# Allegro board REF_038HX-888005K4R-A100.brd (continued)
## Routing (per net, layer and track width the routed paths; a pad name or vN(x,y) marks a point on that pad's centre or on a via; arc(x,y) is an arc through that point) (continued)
D12301: length 268.6
  TOP w0.231: v1(203.52,224.03) 203.32,224.23 SITE2.118
  L03_SIGNAL w0.145: v1(203.52,224.03) 203.52,219.99 202.45,218.92 202.45,210.06 205.53,206.99 205.53,206.13 205.78,205.88 205.78,204.47 206,204.25 206,200.67 205.7,200.36 204.68,200.36 202.45,198.13 202.45,183.27 198,178.81 198,167.65 195.38,165.03 195.38,160.45 188.92,153.99 188.92,141.88 182.51,135.47 182.51,133.73 181.29,132.52 181.29,114.03 179.54,112.28 163.03,112.28 144.41,93.67 144.41,58.48 133.56,47.62 97.42,47.62 D123.01
D12302: length 218.4
  TOP w0.231: SITE2.161 190.93,212.03 v1(189.92,213.03)
  L03_SIGNAL w0.145: D123.02 103.77,70.48 131.14,70.48 134.89,74.23 134.89,119.16 147.59,131.86 147.59,148.59 153.94,154.94 153.94,157.48 156.48,160.02 156.48,161.11 171.08,175.72 171.08,179.07 178.06,186.04 178.06,197.59 183.23,202.76 186.32,202.76 187.02,203.46 187.02,207.77 187.66,208.42 187.66,210.77 v1(189.92,213.03)
D12303: length 258.3
  L03_SIGNAL w0.145: D123.03 101.81,48.32 133.27,48.32 143.72,58.77 143.72,94.15 162.56,112.99 179.27,112.99 180.5,114.22 180.5,132.65 181.81,133.97 181.81,135.95 187.96,142.1 187.96,154.37 193.35,159.75 193.35,168.95 195.11,170.71 195.11,178.93 201.81,185.63 201.81,189.8 200.94,190.66 200.94,197.65 205.16,201.87 205.16,205.6 201.71,209.06 201.71,222.14 v1(202.16,222.59)
D12304: length 212.7
  TOP w0.231: SITE2.160 191.92,212.43 v1(191.32,213.03)
  L03_SIGNAL w0.145: D123.04 108.22,69.85 131.41,69.85 135.52,73.97 135.52,118.9 148.22,131.6 148.22,148.41 155.21,155.39 155.21,157.48 157.75,160.02 157.75,161.19 172.35,175.8 172.35,179.07 179.6,186.31 179.6,197.3 183.79,201.49 186.5,201.49 187.97,202.96 187.97,207.66 188.5,208.2 188.5,210.21 v1(191.32,213.03)
D12305: length 282.8
  TOP w0.231: SITE2.150 198.71,216.43 v1(199.71,217.43)
  L03_SIGNAL w0.145: v1(199.71,217.43) 201.07,216.07 201.07,207.79 204.15,204.71 204.15,201.65 200.31,197.81 200.31,190.4 201.17,189.53 201.17,185.89 194.47,179.2 194.47,171.45 185.83,162.81 185.83,143.21 178.45,135.82 178.45,115.44 177.89,114.88 176.34,114.88 175.66,115.56 175.66,130.86 175.29,131.23 174.14,131.23 173.66,130.75 173.66,116.07 172.71,115.11 162.37,115.11 143.14,95.89 143.14,59.01 133.03,48.89 106.31,48.89 D123.05
D12306: length 215.8
  TOP w0.231: SITE2.159 192.92,212.83 v1(192.72,213.03)
  L03_SIGNAL w0.145: D123.06 102.89,59.44 108.06,59.44 108.3,59.21 108.3,58.16 109.02,57.43 113.18,57.43 113.4,57.65 113.4,65.55 116.43,68.58 131.93,68.58 136.79,73.44 136.79,118.37 149.49,131.07 149.49,144.14 157.11,151.76 157.11,154.31 160.23,157.42 160.23,158.55 173.91,172.23 173.91,176.18 180.87,183.14 180.87,196.77 184.4,200.3 189.17,200.3 190.23,201.36 190.23,210.27 192.55,212.59 192.55,212.86 v1(192.72,213.03)
D12307: length 225.4
  TOP w0.231: SITE2.164 198.71,210.83 199.71,209.83 v1(199.84,209.83)
  L03_SIGNAL w0.145: v1(199.84,209.83) 199.84,209.7 200.23,209.32 200.23,206.84 199.36,205.98 198.89,205.98 198.55,205.64 198.55,205.11 198.91,204.75 198.91,185.9 192.59,179.59 192.59,170.73 185.05,163.19 185.05,160.66 173.62,149.22 173.62,147.95 169.81,144.14 169.81,140.33 162.83,133.35 162.83,132.98 142.51,112.66 142.51,59.27 132.77,49.53 110.76,49.53 D123.07
D12308: length 210.6
  TOP w0.231: SITE2.163 192.92,211.23 v1(192.72,211.03)
  L03_SIGNAL w0.145: v1(192.72,211.03) 191.38,209.7 191.38,199.47 191.7,199.15 191.7,193.96 191.04,193.3 191.04,186.23 185.21,180.39 185.21,177.76 176.77,169.32 174.67,169.32 162.19,156.84 162.19,154.31 159.02,151.13 159.02,148.59 152.03,141.6 152.03,131.23 138.06,117.26 138.06,63.76 137.32,63.02 122.11,63.02 121.01,61.91 121.01,57.85 120.01,56.85 108.52,56.85 D123.08
D12309: length 210.7
  L03_SIGNAL w0.145: v1(198.77,207.69) 198.03,206.94 198.03,205.86 198.02,205.85 198.02,204.89 198.38,204.54 198.38,189.79 198.33,189.74 198.33,186.23 191.95,179.85 191.95,173.27 190.71,172.03 190.71,170.76 179.97,160.02 179.97,159.38 169.81,149.22 169.81,146.69 167.27,144.14 167.27,141.6 158.38,132.71 158.38,130.81 141.87,114.3 141.87,59.54 132.5,50.16 115.2,50.16 D123.09
D12310: length 205.8
  TOP w0.231: SITE2.155 192.92,214.43 v1(192.72,214.63)
  L03_SIGNAL w0.145: v1(192.72,214.63) 191.98,213.89 191.98,212.81 189.6,210.43 189.6,201.63 188.93,200.96 184.15,200.96 180.23,197.03 180.23,185.68 172.99,178.44 172.99,172.3 159.65,158.97 159.65,158.12 156.48,154.94 156.48,152.4 148.86,144.78 148.86,131.34 136.16,118.64 136.16,73.71 131.67,69.22 114.49,69.22 110.7,65.42 110.7,59.75 D123.10
D12311: length 210.4
  TOP w0.231: v1(198.44,209.83) 198.32,209.83 197.72,210.43 SITE2.165
  L03_SIGNAL w0.145: D123.11 119.65,50.8 132.24,50.8 141.24,59.8 141.24,114.56 157.75,131.07 157.75,133.35 166.64,142.24 166.64,144.78 169.18,147.32 169.18,149.86 178.7,159.38 178.7,161.29 191.26,173.84 191.26,180.14 197.58,186.46 197.58,200.99 197.29,201.28 197.29,204.93 197.47,205.12 197.47,208.99 198.32,209.83 v1(198.44,209.83)
D12312: length 282.8
  TOP w0.231: SITE2.151 192.92,216.03 v1(192.72,216.23)
  L03_SIGNAL w0.145: v1(192.72,216.23) 193.45,215.5 193.45,212.62 190.81,209.98 190.81,201.08 189.41,199.68 184.79,199.68 181.57,196.45 181.57,190.33 182.08,189.81 189.74,189.81 190.22,189.33 190.22,187.93 190.01,187.72 184.38,187.72 183.84,187.19 183.84,185.01 184.21,184.64 184.21,178.96 179.41,174.16 178.65,174.16 178.2,174.62 178.2,175.55 181.6,178.94 181.6,179.86 180.99,180.47 179.75,180.47 176.04,176.76 176.04,171.38 174.84,170.18 174.26,170.18 161.56,157.48 161.56,154.94 158.38,151.76 158.38,149.22 150.13,140.97 150.13,130.81 137.43,118.11 137.43,73.18 132.2,67.94 117.48,67.94 116.98,67.45 116.98,66.72 117.31,66.39 134.77,66.39 135.22,66.85 135.22,69.49 135.58,69.85 136.78,69.85 137.29,69.34 137.29,64.82 136.84,64.36 116.68,64.36 116.07,63.75 116.07,59.46 D123.12
D12313: length 202.2
  TOP w0.231: SITE2.166 196.72,210.03 196.92,209.83 v1(197.05,209.83)
  L03_SIGNAL w0.145: D123.13 124.09,51.44 131.98,51.44 140.6,60.06 140.6,116.2 154.57,130.18 154.57,133.99 165.37,144.78 165.37,148.59 172.99,156.21 173.62,156.21 177.43,160.02 177.43,161.29 188.9,172.76 188.9,179.79 196.07,186.96 196.07,190.6 196.75,191.28 196.75,205.14 196.95,205.33 196.95,209.73 v1(197.05,209.83)
D12314: length 198.6
  TOP w0.231: v1(196.92,215.03) 196.72,214.83 SITE2.154
  L03_SIGNAL w0.145: D123.14 126.09,62.32 138.01,62.32 138.7,63 138.7,116.99 152.67,130.96 152.67,138.43 161.56,147.32 161.56,149.86 164.1,152.4 164.1,154.31 167.91,158.12 167.91,159.38 187.05,178.52 187.05,181.41 194.17,188.53 194.17,191.39 194.84,192.07 194.84,201.55 192.56,203.84 192.56,210.05 194.99,212.48 194.99,213.1 v1(196.92,215.03)
D12315: length 196.2
  L03_SIGNAL w0.145: D123.15 128.54,52.07 131.71,52.07 139.97,60.32 139.97,116.47 153.94,130.44 153.94,134.62 164.73,145.41 164.73,149.22 172.99,157.48 172.99,160.66 188.27,175.93 188.27,180.05 195.44,187.22 195.44,190.86 196.11,191.54 196.11,205.48 196.42,205.78 196.42,210.52 196.69,210.79 197.52,210.79 v1(198.36,211.63)
D12316: length 193.6
  TOP w0.231: SITE2.158 196.72,213.23 v1(196.92,213.43)
  L03_SIGNAL w0.145: v1(196.92,213.43) 196.84,213.43 193.19,209.79 193.19,205.82 195.48,203.54 195.48,191.8 194.8,191.12 194.8,187.49 187.63,180.32 187.63,176.57 164.73,153.67 164.73,151.76 162.19,149.22 162.19,146.69 153.3,137.8 153.3,130.7 139.33,116.73 139.33,60.86 138.08,59.61 128.46,59.61 D123.16
D12401: length 381.2
  L03_SIGNAL w0.145: D124.01 97.44,27.29 135.29,27.29 159.98,51.97 159.98,87.43 167.23,94.68 267.03,94.68 276.93,104.57 276.93,143.98 277.28,144.33 277.28,162.51 276.49,163.31 276.49,175.4 274.51,177.38 274.51,191.11 269.23,196.38 261.55,196.38 258.91,199.02 257.8,199.02 256.22,200.6 247.59,200.6 247.28,200.91 v1(229.13,200.91)
D12402: length 279.3
  L03_SIGNAL w0.145: v1(206.12,222.59) 206.12,221.35 203.09,218.32 203.09,210.59 206.95,206.73 206.95,206.03 207.21,205.77 207.21,201.57 207.5,201.28 207.5,200.74 207.25,200.5 207.25,145.61 193.9,132.27 193.9,127.65 190.57,124.31 190.57,102.76 189.59,101.78 163.56,101.78 152.82,91.03 152.82,56.7 139.19,43.07 117.28,43.07 115.98,41.77 115.98,37.49 115.29,36.8 93.01,36.8 D124.02
D12403: length 377.1
  TOP w0.231: UNK2RT9.1 229.13,204.66 v1(229.13,202.81)
  L03_SIGNAL w0.145: D124.03 101.88,27.93 135.03,27.93 159.34,52.24 159.34,87.69 166.96,95.31 266.4,95.31 275.27,104.19 275.27,174.36 273.1,176.53 273.1,190.54 268,195.64 261.39,195.64 258.69,198.34 248.18,198.34 246.39,200.14 228.88,200.14 228.31,200.7 228.31,202 v1(229.13,202.81)
D12404: length 236.3
  TOP w0.231: v1(205.12,199.63) 204.52,200.23 SITE2.18
  L03_SIGNAL w0.145: D124.04 105.68,46.99 133.82,46.99 145.05,58.22 145.05,92.9 162.94,110.79 179.46,110.79 182.55,113.88 182.55,131.15 190.29,138.89 190.29,154.46 196.01,160.19 196.01,164.77 198.63,167.39 198.63,178.55 203.09,183.01 203.09,197.6 v1(205.12,199.63)
D12405: length 340.7
  TOP w0.231: v1(221.32,207.43) 220.72,208.03 SITE2.50
  L03_SIGNAL w0.145: D124.05 106.33,28.56 134.77,28.56 158.71,52.5 158.71,88.02 166.64,95.95 206.07,95.95 226.33,116.2 230.14,116.2 240.93,127 244.74,127 260.62,142.88 261.89,142.88 263.9,144.88 263.9,157.41 UNK2S1_I2C.1
  L22_SIGNAL w0.145: v1(221.32,207.43) 222,208.11 235.33,208.11 239.4,204.03 242.5,204.03 243.38,203.15 243.38,198.34 UNK2K28.3 248.94,196.55 UNK2J4.2
  BOTTOM w0.231: UNK2S1_I2C.1 257.29,157.51 246.01,168.78 246.01,187.23 243.86,189.38 243.86,195.25 UNK2K28.3
D12406: length 195.4
  L03_SIGNAL w0.135: 201.87,158.58 201.87,159.13 200.98,160.02 199.02,160.02 197.75,158.75 197.75,152.25 195.25,149.74 195.25,138.86 185.4,129.02 185.4,108.95 181.81,105.36 163.31,105.36 146.95,89 146.95,56.51 136.1,45.66 106.89,45.66 103.78,42.55 103.78,40.01
  L03_SIGNAL w0.145: D124.06 103.78,40.01 ; 201.87,158.58 202.14,158.31 UNK2K9.2
D12407: length 333.1
  TOP w0.231: v1(222.71,207.43) 221.71,208.43 SITE2.51
  L03_SIGNAL w0.145: UNK2S1_I2C.2 258.71,154.77 258.71,147.95 239.03,128.27 237.12,128.27 205.44,96.58 166.37,96.58 158.07,88.28 158.07,52.76 134.5,29.2 110.77,29.2 D124.07
  L22_SIGNAL w0.145: UNK2K28.6 241.63,196.89 UNK2J5.2 234.92,199.82 234.92,205.54 233.29,207.17 222.98,207.17 v1(222.71,207.43)
  BOTTOM w0.231: UNK2S1_I2C.2 265.67,158.38 265.67,156.72 264.86,155.9 257.8,155.9 245.24,168.46 245.24,186.91 243.09,189.06 243.09,195.43 UNK2K28.6
D12408: length 195.4
  L03_SIGNAL w0.135: 104.19,39.97 104.19,42.38 107.06,45.25 136.27,45.25 147.36,56.35 147.36,88.83 163.48,104.95 181.98,104.95 185.81,108.78 185.81,128.85 195.66,138.69 195.66,149.58 198.16,152.08 198.16,158.58 199.19,159.61 200.81,159.61 201.46,158.96 201.46,158.58
  L03_SIGNAL w0.145: D124.08 106.95,38.92 106.52,39.34 104.82,39.34 104.19,39.97 ; 201.46,158.58 201.19,158.31 UNK2K9.7
D12409: length 342.5
  TOP w0.231: SITE2.19 204.92,201.23 v1(205.12,201.03)
  L03_SIGNAL w0.145: UNK2S1_RST_N.1 256.13,192.09 256.13,167.58 257.99,165.72 257.99,155.92 256.17,154.11 256.17,150.5 234.58,128.91 233.12,128.91 201.43,97.22 166.11,97.22 157.44,88.55 157.44,53.03 134.24,29.83 115.22,29.83 D124.09
  L22_SIGNAL w0.145: v1(205.12,201.03) 205.83,200.32 225.97,200.32 226.43,199.86 229.74,199.86 238.07,191.53 251.36,191.53 258.1,198.27 260.32,198.27 UNK2K10.3
  BOTTOM w0.231: UNK2K10.3 263.51,198.25 263.51,196.62 262.96,196.07 260.11,196.07 UNK2S1_RST_N.1
D12410: length 233.3
  TOP w0.231: SITE2.24 206.92,201.23 v1(206.72,201.03)
  L03_SIGNAL w0.145: v1(206.72,201.03) 206.72,199.35 204,196.63 204,192.54 204.71,191.83 204.71,185.85 205.32,185.25 205.32,145.09 192.45,132.23 192.45,130.36 188.25,126.16 188.25,103.58 187.11,102.44 162.91,102.44 152.03,91.57 152.03,57.02 138.79,43.79 115.34,43.79 113.65,42.1 113.65,39.72 D124.10
D12411: length 219.9
  L03_SIGNAL w0.145: D124.11 119.6,30.53 133.95,30.53 156.8,53.38 156.8,88.81 165.85,97.85 200.8,97.85 214.26,111.32 214.26,133.35 215.53,134.62 215.53,137.16 224.14,145.76 224.14,169.5 UNK2K14.2
D12412: length 234
  L03_SIGNAL w0.145: D124.12 121.4,42.39 139.47,42.39 153.5,56.42 153.5,90.75 163.85,101.1 190.32,101.1 191.58,102.35 191.58,123.92 195.07,127.4 195.07,129.98 207.93,142.85 207.93,199.72 208.55,200.33 208.55,205.02 208.44,205.13 208.44,206.82 v1(207.57,207.69)
D12413: length 219.9
  L03_SIGNAL w0.145: UNK2K14.7 220.85,169.41 220.85,151.08 214.32,144.55 214.32,141.18 209.92,136.78 209.92,134.02 208.6,132.71 208.6,125.82 208.1,125.31 206.28,125.31 205.95,125.64 205.95,127.76 205.46,128.25 204.15,128.25 202.73,126.83 202.73,101.12 200.1,98.49 165.58,98.49 156.17,89.07 156.17,53.65 133.69,31.17 124.04,31.17 D124.13
D12414: length 230.6
  L03_SIGNAL w0.145: v1(209.97,207.69) 209.29,207 209.29,205.99 209.7,205.58 209.7,199.94 208.61,198.85 208.61,142.57 196.73,130.7 196.73,125.16 192.4,120.83 192.4,101.15 191.67,100.42 164.13,100.42 154.17,90.47 154.17,56.14 139.75,41.71 125.8,41.71 D124.14
D12415: length 219.9
  L03_SIGNAL w0.145: D124.15 128.49,31.8 133.42,31.8 155.53,53.91 155.53,89.34 165.32,99.12 197.19,99.12 200.6,102.53 200.6,126.72 201.83,127.95 201.83,132.3 212.74,143.21 212.74,158.99 213.43,159.69 214.99,159.69 215.56,159.12 215.56,153.14 216.32,152.38 217.77,152.38 218.43,153.04 218.43,169.35 UNK2K15.2
D12416: length 219.9
  L03_SIGNAL w0.145: UNK2K15.7 213.62,170.31 211.02,170.31 210.06,169.35 210.06,142.01 197.61,129.56 197.61,124.8 197.97,124.44 197.97,102.9 197.56,102.49 196.06,102.49 195.32,103.23 195.32,115.06 194.88,115.5 194.02,115.5 193.75,115.23 193.75,100.45 193.06,99.76 165.06,99.76 154.9,89.6 154.9,55.83 138.9,39.83 129,39.83 D124.16
D30102: length 142.6
  TOP w0.254: SITE1.26 127.72,195.68 127.69,195.65 127.69,179.35 arc(127.75,179.07) 127.9,178.84 151.75,155 164.87,141.87 167.69,139.05 167.69,103.16 arc(167.51,102.26) 167,101.49 166.92,101.41 arc(166.54,101.16) 166.09,101.07 163.31,101.07 arc(161.29,100.23) 160.45,98.21 arc(161.16,96.5) 162.87,95.79 166.79,95.79 arc(167.01,95.75) 167.19,95.62 arc(167.56,95.07) 167.69,94.42 167.69,91.43 arc(167.65,91.24) 167.54,91.07
  TOP w0.31: D301.02 167.54,91.07
D30104: length 142.7
  TOP w0.254: SITE1.27 128.12,195.68 128.15,195.65 128.15,179.35 arc(128.17,179.25) 128.22,179.17 168.15,139.24 168.15,103.16 arc(167.93,102.08) 167.32,101.17 167.24,101.09 arc(166.71,100.74) 166.09,100.61 163.31,100.61 arc(161.61,99.91) 160.9,98.21 arc(161.48,96.82) 162.87,96.25 166.79,96.25 arc(167.18,96.17) 167.51,95.95 arc(167.98,95.25) 168.15,94.42 168.15,91.41 arc(168.19,91.22) 168.3,91.05
  TOP w0.31: D301.04 168.3,91.05
D30106: length 142.7
  TOP w0.254: SITE1.29 128.92,196.58 130.2,195.3 arc(130.25,195.22) 130.27,195.12 130.27,180.44 arc(130.33,180.16) 130.48,179.93 174.59,135.82 177.78,132.64 arc(177.83,132.55) 177.85,132.46 177.85,101.88 arc(177.77,101.46) 177.53,101.1 arc(177.36,100.98) 177.16,100.95 174.92,100.95 arc(173.68,100.43) 173.17,99.19 173.17,97.09 arc(173.63,95.97) 174.75,95.5 177.09,95.5 arc(177.63,95.28) 177.85,94.74 177.85,91.43 arc(177.81,91.24) 177.7,91.08
  TOP w0.31: D301.06 177.7,91.08
D30108: length 142.6
  TOP w0.254: SITE1.30 129.32,196.82 130.52,195.62 arc(130.68,195.39) 130.73,195.12 130.73,180.44 arc(130.75,180.34) 130.81,180.26 178.1,132.96 arc(178.26,132.73) 178.31,132.46 178.31,101.88 arc(178.19,101.28) 177.85,100.77 arc(177.54,100.56) 177.16,100.49 174.92,100.49 arc(174,100.11) 173.62,99.19 173.62,97.09 arc(173.95,96.29) 174.75,95.96 177.09,95.96 arc(177.95,95.6) 178.31,94.74 178.31,91.41 arc(178.35,91.21) 178.46,91.05
  TOP w0.31: D301.08 178.46,91.05
D30110: length 142.7
  TOP w0.254: SITE1.32 130.12,199.73 133.59,196.26 arc(133.65,196.18) 133.66,196.08 133.66,180.97 arc(133.72,180.7) 133.87,180.47 183.01,131.33 187.94,126.4 arc(187.99,126.32) 188.01,126.22 188.01,100.28 arc(187.85,99.89) 187.47,99.73 186.58,99.73 arc(185.7,99.36) 185.33,98.47 185.33,97.17 arc(185.73,96.21) 186.69,95.81 187.02,95.81 arc(187.36,95.74) 187.65,95.55 arc(187.92,95.14) 188.01,94.67 188.01,94.67 188.01,91.44 arc(187.98,91.24) 187.87,91.08
  TOP w0.31: D301.10 187.87,91.08
D30112: length 142.6
  TOP w0.254: SITE1.33 130.52,199.98 133.91,196.58 arc(134.07,196.35) 134.12,196.08 134.12,180.97 arc(134.14,180.87) 134.2,180.79 183.33,131.65 188.26,126.72 arc(188.42,126.49) 188.47,126.22 188.47,100.28 arc(188.18,99.57) 187.47,99.27 186.58,99.27 arc(186.02,99.04) 185.79,98.47 185.79,97.17 arc(186.05,96.53) 186.69,96.27 187.02,96.27 arc(187.53,96.16) 187.97,95.87 arc(188.34,95.32) 188.47,94.67 188.47,91.41 arc(188.51,91.21) 188.62,91.05
  TOP w0.31: D301.12 188.62,91.05
D30114: length 142.7
  TOP w0.254: SITE1.35 131.32,200.98 136.04,196.26 arc(136.1,196.18) 136.12,196.08 136.12,182.9 arc(136.26,182.16) 136.68,181.53 197.38,120.84 arc(197.97,119.96) 198.17,118.92 198.17,91.44 arc(198.14,91.24) 198.03,91.08
  TOP w0.31: D301.14 198.03,91.08
D30116: length 142.6
  TOP w0.254: SITE1.36 131.72,201.23 136.37,196.58 arc(136.52,196.35) 136.57,196.08 136.57,182.9 arc(136.69,182.34) 137.01,181.86 197.7,121.16 arc(198.39,120.13) 198.63,118.92 198.63,91.41 arc(198.67,91.21) 198.78,91.05
  TOP w0.31: D301.16 198.78,91.05
D30502: length 142.7
  TOP w0.254: SITE2.26 207.72,195.68 207.69,195.65 207.69,142.86 arc(207.75,142.59) 207.9,142.36 241.28,108.98 arc(241.33,108.9) 241.35,108.8 241.35,100.21 arc(241.33,100.11) 241.28,100.03 240.42,99.18 arc(240.34,99.12) 240.24,99.1 235.04,99.1 arc(234.38,98.97) 233.83,98.6 233.41,98.18 arc(233.22,97.89) 233.15,97.55 233.15,97.26 arc(233.25,96.75) 233.54,96.32 233.59,96.27 arc(234.34,95.77) 235.22,95.6 240.24,95.6 arc(240.34,95.58) 240.42,95.52 241.28,94.67 arc(241.33,94.59) 241.35,94.49 241.35,91.43 arc(241.31,91.24) 241.2,91.07
  TOP w0.31: D305.02 241.2,91.07
D30504: length 142.6
  TOP w0.254: SITE2.27 208.12,195.68 208.15,195.65 208.15,142.86 arc(208.17,142.77) 208.22,142.68 241.6,109.31 arc(241.75,109.08) 241.81,108.8 241.81,100.21 arc(241.75,99.94) 241.6,99.71 240.75,98.85 arc(240.51,98.7) 240.24,98.64 235.04,98.64 arc(234.56,98.55) 234.15,98.28 233.73,97.86 arc(233.64,97.72) 233.6,97.55 233.6,97.26 arc(233.67,96.93) 233.86,96.65 233.91,96.6 arc(234.51,96.19) 235.22,96.05 240.24,96.05 arc(240.51,96) 240.75,95.84 241.6,94.99 arc(241.75,94.76) 241.81,94.49 241.81,91.41 arc(241.85,91.22) 241.96,91.05
  TOP w0.31: D305.04 241.96,91.05
D30506: length 142.6
  TOP w0.254: SITE2.29 208.92,196.58 210.2,195.3 arc(210.25,195.22) 210.27,195.12 210.27,144.13 arc(210.33,143.86) 210.48,143.63 251.38,102.73 arc(251.48,102.58) 251.51,102.4 251.51,100.4 arc(251.27,99.8) 250.67,99.55 247.3,99.55 arc(246.1,99.06) 245.61,97.86 245.61,97.04 arc(245.69,96.62) 245.93,96.27 arc(246.51,95.88) 247.19,95.75 251.01,95.75 arc(251.37,95.6) 251.51,95.24 251.51,91.44 arc(251.48,91.24) 251.37,91.08
  TOP w0.31: D305.06 251.37,91.08
D30508: length 142.6
  TOP w0.254: SITE2.30 209.32,196.82 210.52,195.62 arc(210.68,195.39) 210.73,195.12 210.73,144.13 arc(210.75,144.03) 210.81,143.95 251.7,103.05 arc(251.9,102.76) 251.97,102.41 251.97,100.4 arc(251.59,99.48) 250.67,99.1 247.3,99.1 arc(246.43,98.73) 246.06,97.86 246.06,97.04 arc(246.11,96.8) 246.25,96.59 arc(246.68,96.31) 247.19,96.2 251.01,96.2 arc(251.69,95.92) 251.97,95.24 251.97,91.41 arc(252.01,91.21) 252.12,91.05
  TOP w0.31: D305.08 252.12,91.05
D30510: length 142.7
  TOP w0.254: SITE2.32 210.12,199.73 213.59,196.26 arc(213.65,196.18) 213.66,196.08 213.66,190.55 arc(213.72,190.28) 213.87,190.05 261.6,142.32 arc(261.66,142.24) 261.67,142.14 261.67,100.02 arc(261.3,99.12) 260.41,98.75 259.09,98.75 arc(257.9,98.26) 257.4,97.07 257.4,96.62 arc(257.85,95.54) 258.93,95.1 260.57,95.1 arc(261.04,95) 261.43,94.74 arc(261.61,94.47) 261.67,94.16 261.67,91.44 arc(261.64,91.24) 261.53,91.08
  TOP w0.31: D305.10 261.53,91.08
D30512: length 142.6
  TOP w0.254: SITE2.33 210.52,199.98 213.91,196.58 arc(214.07,196.35) 214.12,196.08 214.12,190.55 arc(214.14,190.46) 214.2,190.37 261.92,142.65 arc(262.08,142.42) 262.13,142.14 262.13,100.02 arc(261.63,98.8) 260.41,98.3 259.09,98.3 arc(258.22,97.94) 257.86,97.07 257.86,96.62 arc(258.17,95.87) 258.93,95.55 260.57,95.55 arc(261.21,95.43) 261.76,95.06 arc(262.03,94.65) 262.13,94.16 262.13,91.41 arc(262.17,91.21) 262.28,91.05
  TOP w0.31: D305.12 262.28,91.05
D30514: length 142.7
  TOP w0.254: SITE2.35 211.32,200.98 216.04,196.26 arc(216.1,196.18) 216.12,196.08 216.12,191.57 arc(216.17,191.3) 216.32,191.07 271.76,135.63 arc(271.81,135.55) 271.83,135.45 271.83,99.21 arc(271.6,98.65) 271.04,98.41 270.97,98.41 arc(270.06,98.03) 269.68,97.12 269.68,96.81 arc(270.03,95.95) 270.88,95.6 270.98,95.6 arc(271.2,95.56) 271.38,95.43 271.54,95.27 arc(271.76,94.95) 271.83,94.57 271.83,91.44 arc(271.8,91.24) 271.69,91.08
  TOP w0.31: D305.14 271.69,91.08
D30516: length 142.6
  TOP w0.254: SITE2.36 211.72,201.23 216.36,196.58 arc(216.52,196.35) 216.57,196.08 216.57,191.57 arc(216.59,191.47) 216.65,191.39 272.08,135.95 arc(272.24,135.72) 272.29,135.45 272.29,99.21 arc(271.92,98.32) 271.04,97.95 270.97,97.95 arc(270.38,97.71) 270.14,97.12 270.14,96.81 arc(270.35,96.28) 270.88,96.06 270.98,96.06 arc(271.37,95.98) 271.71,95.76 271.87,95.6 arc(272.18,95.13) 272.29,94.57 272.29,91.41 arc(272.33,91.21) 272.44,91.05
  TOP w0.31: D305.16 272.44,91.05
MSDPS1_TRVB-: length 5.5
  TOP w0.203: SB1.2 258.08,15.24 DPS1.B09
MSDPS2_TRVB-: length 5.1
  TOP w0.203: DPS2.B09 184.42,414.02 SB2.2
MSDPS3_TRVB-: length 4.8
  TOP w0.203: DPS3.B09 110.76,15.24 SB3.2
MSDPS8_TRVB-: length 5.6
  TOP w0.203: SB8.2 34.56,414.02 DPS8.B09
S1_1AUX+: length 2.4
  BOTTOM w0.203: R129.1 K9.4
S1_1AUX-: length 2.4
  BOTTOM w0.203: R130.1 K9.5
S1_1SPI_CSN: length 11.1
  BOTTOM w0.231: K19.6 128.59,144.99 128.59,152.72 K15.5
S1_1SPI_SCK: length 11.1
  BOTTOM w0.231: K19.3 129.4,144.99 129.4,152.72 K15.4
S1_1SPI_SDI: length 11.1
  BOTTOM w0.231: K20.6 136.72,144.99 136.72,152.72 K14.5
S1_1SPI_SDO: length 11.1
  BOTTOM w0.231: K14.4 137.53,152.72 137.53,144.99 K20.3
S1_2AUX+: length 22.5
  BOTTOM w0.203: R129.2 R3.1 121.94,150.09 121.94,130.82 R1.2 C3.1
S1_2AUX-: length 22.5
  BOTTOM w0.203: R130.2 R2.2 121.39,150.09 121.39,130.82 R4.2 C4.1
S1_AUXCH+: length 58
  TOP w0.203: SITE1.21 125.72,206.2 v2(126.09,206.57)
  BOTTOM w0.203: K9.3 122.34,156.11 121.94,156.52 121.94,167.11 K12.3 121.94,169.76 121.94,178.02 123.06,179.14 123.06,201.79 125.79,204.52 125.79,206.28 v2(126.09,206.57)
S1_AUXCH-: length 58
  TOP w0.203: SITE1.20 125.32,206.2 v2(124.95,206.57)
  BOTTOM w0.203: v2(124.95,206.57) 125.25,206.28 125.25,204.75 122.51,202.02 122.51,179.37 121.39,178.24 121.39,169.76 K12.6 121.39,167.11 121.39,156.52 120.98,156.11 K9.6
S1_ISP_1LOCK: length 73.7
  TOP w0.231: R118.2 v1(104.89,215.39)
  L22_SIGNAL w0.145: K33.3 54.91,187.17 80.64,212.9 102.4,212.9 v1(104.89,215.39)
S1_SPI_1_CSN: length 85.8
  L22_SIGNAL w0.145: U1.1 79.75,142.42 81.05,143.73 85.8,143.73 91.97,137.55 117.61,137.55 123.34,143.29 123.34,143.94 122.73,144.55 121.95,144.55 119.71,142.32 118.88,142.32 118.46,142.73 118.46,143.34 121.11,145.99 K19.7
  BOTTOM w0.231: U1.1 75.93,141.16 75.93,131.53 75,130.61 R87.1
S1_SPI_1_SCK: length 85.8
  L22_SIGNAL w0.145: K19.2 128.97,147.62 115.55,147.62 114.61,146.69 114.61,139.9 113.76,139.04 111.12,139.04 110.29,139.87 110.29,145.66 109.7,146.26 108.18,146.26 107.51,145.59 107.51,139.63 106.92,139.04 104.69,139.04 104.08,139.65 104.08,150.23 102.87,151.44 92.35,151.44 87.21,146.3 83.49,146.3 U1.6
  BOTTOM w0.231: U1.6 R91.1
S1_SPI_1_SDI: length 2.1
  BOTTOM w0.231: K20.7 R127.1
S1_SPI_1_SDO: length 2.1
  BOTTOM w0.231: K20.2 R125.1
S1_SPI_2_CSN: length 120.2
  L22_SIGNAL w0.145: K19.5 120.52,134.72 86.15,134.72 83.85,137.02 77.4,137.02 76.62,137.79 72.04,137.79 71.25,138.58 69.01,138.58 67.41,136.98 61.64,136.98 60.71,136.05 60.71,131 60.32,130.61 58.82,130.61 58.28,131.14 58.28,137.79 59.72,139.23 59.72,147.31 59.27,147.76 57.41,147.76 56.99,147.34 56.99,143 56.41,142.42 U2.1
  BOTTOM w0.231: U2.1 53.1,140.56 53.1,132.76 54.11,131.75 R94.1
S1_SPI_2_SCK: length 120.2
  L22_SIGNAL w0.145: U2.6 64.65,145.42 64.65,141.71 65.72,140.64 67.58,140.64 68.33,141.38 68.33,160.55 69.06,161.28 71.1,161.28 71.89,160.49 71.89,141.15 72.4,140.64 84.79,140.64 89.27,136.16 118.87,136.16 125.41,142.69 128.45,142.69 129.55,141.59 K19.4
  BOTTOM w0.231: U2.6 R98.1
S1_SPI_2_SDI: length 2.1
  BOTTOM w0.231: K20.5 R128.1
S1_SPI_2_SDO: length 2.1
  BOTTOM w0.231: K20.4 R126.1
S1_SPI_11_SDI: length 83.7
  L22_SIGNAL w0.145: U1.2 78.48,148.77 83.02,148.77 84.14,149.89 84.14,150.12 87,152.98 115.22,152.98 118.7,149.5 124.67,149.5 126.03,150.86 131.3,150.86 133.44,148.72 v1(133.44,144.99)
  BOTTOM w0.231: R88.1 74.59,132.76 74.59,139.56 73.11,141.04 73.11,143.41 U1.2
S1_SPI_11_SDO: length 83.7
  L22_SIGNAL w0.145: v1(140.81,144.99) 140.34,145.46 140.34,150.98 139.22,152.1 118.85,152.1 113.3,157.65 110.37,157.65 107.2,160.82 102.54,160.82 100.86,162.5 93.06,162.5 91.92,163.64 88.24,163.64 87.3,162.7 84.45,162.7 82.29,160.54 U1.5
  BOTTOM w0.231: U1.5 R92.1
S1_SPI_22_SDI: length 118.1
  L22_SIGNAL w0.145: U2.2 52.9,142.9 52.9,132.85 56.62,129.13 86.71,129.13 89.75,132.17 121.27,132.17 128.27,139.17 132.01,139.17 v1(133.44,140.59)
  BOTTOM w0.231: R95.1 53.64,130.61 52.29,131.95 52.29,142.29 U2.2
S1_SPI_22_SDO: length 118.1
  L22_SIGNAL w0.145: v1(140.81,140.59) 142.24,142.03 142.24,160.55 139.62,163.18 107.4,163.18 105.46,165.12 65.24,165.12 62.58,162.45 U2.5
  BOTTOM w0.231: U2.5 R99.1
S1_SPI_CSN: length 62.9
  TOP w0.231: SITE1.43 134.52,201.23 v1(134.72,201.03)
  BOTTOM w0.231: v1(134.72,201.03) 133.89,201.03 130.66,204.25 129.06,204.25 128.4,203.59 128.4,191.11 127.73,190.44 126.1,190.44 125.6,189.95 125.6,165.55 126.21,164.94 128.35,164.94 128.85,164.44 128.85,157.56 K15.6
S1_SPI_SCK: length 62.9
  TOP w0.231: v1(134.32,205.23) 134.12,205.03 SITE1.42
  BOTTOM w0.231: K15.3 132.41,157.93 132.41,166.72 131.87,167.26 130.35,167.26 129.77,167.84 129.77,176.83 128.06,178.54 128.06,187.32 128.59,187.85 129.89,187.85 130.52,188.48 130.52,198.39 131.41,199.27 132.66,199.27 133.39,198.54 135.45,198.54 136.02,199.11 136.02,202.28 134.32,203.98 v1(134.32,205.23)
S1_SPI_SDI: length 62.9
  TOP w0.231: SITE1.44 134.92,206.03 v1(134.32,206.63)
  BOTTOM w0.231: v1(134.32,206.63) 138.09,202.86 138.09,197.63 137.53,197.06 134.34,197.06 133.56,196.28 133.56,181.53 132.15,180.12 132.15,178.17 133.67,176.65 133.67,173.29 134.98,171.97 134.98,167.29 136.95,165.33 136.95,157.22 135.84,156.11 K14.6
S1_SPI_SDO: length 62.9
  TOP w0.231: SITE1.41 133.72,206.03 v1(133.12,206.63)
  BOTTOM w0.231: v1(133.12,206.63) 134.32,207.83 136.99,207.83 137.78,207.04 137.78,205.83 140.21,203.4 140.21,180.32 139.37,179.48 139.37,173.15 139.03,172.81 139.03,168.02 140.39,166.66 140.39,157.78 K14.3
S1_XTAL_IN: length 37.5
  TOP w0.231: SITE1.109 126.92,228.03 v1(127.12,228.23)
  BOTTOM w0.231: v1(102.86,243.18) 102.86,244.44 103.65,245.24 110.47,245.24 114.43,241.27 114.43,237.1 123.31,228.23 v1(127.12,228.23)
S1_XTAL_OUT: length 39.9
  TOP w0.231: v1(127.12,229.63) 126.52,229.03 SITE1.110
  BOTTOM w0.231: v1(102.86,248.48) 102.86,247.17 103.68,246.35 114.29,246.35 116.29,244.36 116.29,242.93 118.08,241.15 118.08,236.87 125.32,229.63 v1(127.12,229.63)
S2_1AUX+: length 2.4
  BOTTOM w0.203: UNK2K9.4 UNK2R129.1
S2_1AUX-: length 2.4
  BOTTOM w0.203: UNK2K9.5 UNK2R130.1
S2_1SPI_CSN: length 11.1
  BOTTOM w0.231: UNK2K15.5 215.14,165.04 215.14,157.31 UNK2K19.6
S2_1SPI_SCK: length 11.1
  BOTTOM w0.231: UNK2K15.4 215.95,165.04 215.95,157.31 UNK2K19.3
S2_1SPI_SDI: length 11.1
  BOTTOM w0.231: UNK2K14.5 223.27,165.04 223.27,157.31 UNK2K20.6
S2_1SPI_SDO: length 11.1
  BOTTOM w0.231: UNK2K14.4 224.08,165.04 224.08,157.31 UNK2K20.3
S2_2AUX+: length 22.5
  BOTTOM w0.203: UNK2C3.1 UNK2R1.2 201.94,130.82 201.94,150.09 UNK2R3.1 UNK2R129.2
S2_2AUX-: length 22.5
  BOTTOM w0.203: UNK2R130.2 UNK2R2.2 201.39,150.09 201.39,130.82 UNK2R4.2 UNK2C4.1
S2_AUXCH+: length 58
  TOP w0.203: SITE2.21 205.72,206.2 v2(206.09,206.57)
  BOTTOM w0.203: UNK2K9.3 202.34,156.11 201.94,156.52 201.94,167.11 UNK2K12.3 201.94,169.76 201.94,177.44 202.98,178.49 202.98,201.01 205.79,203.82 205.79,206.28 v2(206.09,206.57)
S2_AUXCH-: length 58
  TOP w0.203: SITE2.20 205.32,206.2 v2(204.95,206.57)
  BOTTOM w0.203: UNK2K9.6 200.98,156.11 201.39,156.52 201.39,167.11 UNK2K12.6 201.39,169.76 201.39,177.67 202.43,178.72 202.43,201.24 205.25,204.05 205.25,206.28 v2(204.95,206.57)
S2_ISP_1LOCK: length 70.6
  TOP w0.231: UNK2R118.2 v1(184.89,215.39)
  L22_SIGNAL w0.145: UNK2K33.3 244.18,208.25 243.56,208.87 243.56,211.56 242.91,212.22 231.04,212.22 229.34,210.53 226.16,210.53 223.34,213.35 219.36,213.35 214.4,218.31 211.83,218.31 210.07,220.07 191.77,220.07 187.76,216.07 185.57,216.07 v1(184.89,215.39)
S2_SPI_1_CSN: length 85.8
  L22_SIGNAL w0.145: UNK2K19.7 215.55,159.92 215.55,179.94 219.4,183.78 228.49,183.78 229.44,182.84 233.47,182.84 235.34,180.97 235.34,176.93 236.91,175.37 243.54,175.37 246.33,178.16 255.05,178.16 256.66,176.56 UNK2U1.1
  BOTTOM w0.231: UNK2U1.1 257.75,177.07 257.75,185.63 UNK2R87.1
S2_SPI_1_SCK: length 85.8
  L22_SIGNAL w0.145: UNK2U1.6 249.09,171.48 247.8,170.19 246.35,170.19 245.11,171.43 234.76,171.43 233.92,170.59 231.95,170.59 230.07,168.71 230.07,166.57 231.24,165.41 239.33,165.41 240.1,166.19 249.57,166.19 250.37,165.38 250.37,163.93 249.91,163.47 242.08,163.47 241.16,162.55 229.12,162.55 226.5,159.93 218.76,159.93 UNK2K19.2
  BOTTOM w0.231: UNK2U1.6 UNK2R91.1
S2_SPI_1_SDI: length 2.1
  BOTTOM w0.231: UNK2K20.7 UNK2R127.1
S2_SPI_1_SDO: length 2.1
  BOTTOM w0.231: UNK2K20.2 UNK2R125.1
S2_SPI_2_CSN: length 120.2
  L22_SIGNAL w0.145: UNK2K19.5 213.94,148.97 215.73,147.19 228.41,147.19 232.73,151.52 241.07,151.52 248.18,144.41 253.37,144.41 254.62,143.15 271.99,143.15 275.13,146.29 275.13,153.83 279.89,158.59 279.89,174.65 UNK2U2.1
  BOTTOM w0.231: UNK2R94.1 278.92,187.23 279.85,186.29 279.85,178.43 UNK2U2.1
S2_SPI_2_SCK: length 120.2
  L22_SIGNAL w0.145: UNK2U2.6 268.74,171.48 268.3,171.91 268.3,177.64 267.64,178.3 266.31,178.3 265.37,179.24 265.37,184.83 264.87,185.33 263.93,185.33 263.43,184.83 263.43,178.78 262.94,178.3 258.99,178.3 255.31,181.98 246.01,181.98 245.04,182.96 245.04,185.09 243.73,186.4 217.88,186.4 212.79,181.31 212.79,179.02 210.04,176.27 210.04,155.69 210.72,155.01 216.04,155.01 UNK2K19.4
  BOTTOM w0.231: UNK2U2.6 UNK2R98.1
S2_SPI_2_SDI: length 2.1
  BOTTOM w0.231: UNK2K20.5 UNK2R128.1
S2_SPI_2_SDO: length 2.1
  BOTTOM w0.231: UNK2K20.4 UNK2R126.1
S2_SPI_11_SDI: length 83.7
  L22_SIGNAL w0.145: UNK2U1.2 261.47,170.81 261.47,157.35 257.25,153.13 250.42,153.13 246.27,157.28 237.04,157.28 236.14,156.38 228.76,156.38 227.4,155.02 220.52,155.02 219.99,155.55 v1(219.99,157.31)
  BOTTOM w0.231: UNK2U1.2 257.34,174.02 255.96,175.39 255.96,186.03 258.31,188.37 UNK2R88.1
S2_SPI_11_SDO: length 83.7
  L22_SIGNAL w0.145: v1(227.36,157.31) 228.36,158.31 235.65,158.31 237.87,160.53 243.93,160.53 244.46,161.06 246.61,161.06 251.7,155.96 256.98,155.96 259.08,158.06 259.08,166.55 258.37,167.25 256.52,167.25 256.04,166.77 256.04,158.24 255.46,157.66 254.02,157.66 253.69,157.98 253.69,167.52 255.57,169.39 255.57,171.97 255.05,172.5 253.64,172.5 253.14,172.01 253.14,171.44 UNK2U1.5
  BOTTOM w0.231: UNK2U1.5 UNK2R92.1
S2_SPI_22_SDI: length 118.1
  L22_SIGNAL w0.145: v1(219.99,152.91) 219.27,152.2 217.18,152.2 216.64,151.66 216.64,149.27 217.09,148.82 227.75,148.82 232.18,153.25 241.55,153.25 248.61,146.19 253.95,146.19 254.53,145.6 271.33,145.6 272.2,146.48 272.2,155.71 275.21,158.72 275.21,173.42 276.26,174.47 277.52,174.47 UNK2U2.2
  BOTTOM w0.231: UNK2R95.1 279.97,188.37 281.18,187.15 281.18,177.23 UNK2U2.2
S2_SPI_22_SDO: length 118.1
  L22_SIGNAL w0.145: v1(227.36,152.91) 226.73,152.29 224.55,152.29 224.17,151.9 224.17,150.67 224.58,150.26 226.94,150.26 231.4,154.73 243.65,154.73 250.17,148.21 263.25,148.21 263.9,147.55 269.18,147.55 270.05,148.43 270.05,156.64 273.55,160.14 273.55,177.06 273.29,177.32 272.33,177.32 272.11,177.1 272.11,160.93 271.51,160.33 269.86,160.33 269.46,160.73 269.46,168.04 UNK2U2.5
  BOTTOM w0.231: UNK2U2.5 UNK2R99.1
S2_SPI_CSN: length 62.9
  TOP w0.231: SITE2.43 214.52,201.23 v1(214.72,201.03)
  BOTTOM w0.231: UNK2K15.6 215.05,168.43 215.46,168.84 215.46,175.23 215.05,175.64 205.77,175.64 205.35,176.07 205.35,192.12 205.88,192.65 207.55,192.65 207.93,193.02 207.93,205.46 208.26,205.79 210.39,205.79 210.69,205.49 210.69,202.88 211.55,202.02 214.27,202.02 214.72,201.57 v1(214.72,201.03)
S2_SPI_SCK: length 62.9
  TOP w0.231: SITE2.42 214.12,205.03 v1(214.32,205.23)
  BOTTOM w0.231: UNK2K15.3 219.2,170.49 219.2,176.3 217.92,177.59 208.47,177.59 207.94,178.12 207.94,190.27 208.44,190.77 210.42,190.77 210.9,191.25 210.9,194.41 209.41,195.89 209.41,201.09 209.81,201.49 210.37,201.49 210.78,201.09 210.78,200.05 211.17,199.65 215.12,199.65 216.16,200.7 216.16,202.25 214.32,204.09 v1(214.32,205.23)
S2_SPI_SDI: length 62.9
  TOP w0.231: SITE2.44 214.92,206.03 v1(214.32,206.63)
  BOTTOM w0.231: v1(214.32,206.63) 217.1,203.85 218.34,203.85 218.71,203.47 218.71,198.71 218.17,198.17 214.51,198.17 213.77,197.44 213.77,188.72 213.21,188.16 211.13,188.16 210.51,187.54 210.51,180.92 210.95,180.49 219.98,180.49 223.51,176.95 223.51,169.2 222.74,168.43 UNK2K14.6
S2_SPI_SDO: length 62.9
  TOP w0.231: SITE2.41 213.72,206.03 v1(213.12,206.63)
  BOTTOM w0.231: v1(213.12,206.63) 214.36,207.87 218.07,207.87 218.7,207.24 218.7,205.68 220.32,204.07 220.32,197.19 219.83,196.7 216.81,196.7 216.5,196.39 216.5,186.52 214.62,184.64 214.62,182.94 215.04,182.52 221.22,182.52 226.68,177.06 226.68,169.84 UNK2K14.3
S2_XTAL_IN: length 37.5
  TOP w0.231: v1(207.12,228.23) 206.92,228.03 SITE2.109
  BOTTOM w0.231: v1(182.86,243.18) 182.86,244.44 183.65,245.24 190.47,245.24 194.43,241.27 194.43,237.1 203.31,228.23 v1(207.12,228.23)
S2_XTAL_OUT: length 39.9
  TOP w0.231: v1(207.12,229.63) 206.52,229.03 SITE2.110
  BOTTOM w0.231: v1(207.12,229.63) 205.32,229.63 198.08,236.87 198.08,241.15 196.29,242.93 196.29,244.36 194.29,246.35 183.68,246.35 182.86,247.17 v1(182.86,248.48)
SK1_2: length 3.3
  TOP w0.231: SK1.2 83.1,136.21 SK1_2.1
SK1_3: length 3
  TOP w0.231: SK1.3 SK1_3.1
SK1_4: length 3.3
  TOP w0.231: SK1.4 83.1,130.19 SK1_4.1
SK1_5: length 3.3
  TOP w0.231: SK1.5 78.28,130.19 SK1_5.1
SK1_6: length 3
  TOP w0.231: SK1.6 SK1_6.1
SK1_7: length 3.3
  TOP w0.231: SK1.7 78.28,136.21 SK1_7.1
SK2_2: length 3.3
  TOP w0.231: SK2.2 66.59,136.21 SK2_2.1
SK2_3: length 3
  TOP w0.231: SK2.3 SK2_3.1
SK2_4: length 3.3
  TOP w0.231: SK2.4 66.59,130.19 SK2_4.1
SK2_5: length 3.3
  TOP w0.231: SK2_5.1 61.77,130.19 SK2.5
SK2_6: length 3
  TOP w0.231: SK2.6 SK2_6.1
SK2_7: length 3.3
  TOP w0.231: SK2.7 61.77,136.21 SK2_7.1
UDBGND: length 2.8
  BOTTOM w0.508: v1(68.85,15.25) 69.24,14.86 UB1.7
  vias: v1(13.13,290.5) v1(14.87,290.12) v1(15.11,291.63) v1(16.35,138.43) v1(16.52,153.59) v1(16.52,150.51) v1(16.52,147.42) v1(16.51,141.08) v1(18.25,140.7) v1(18.49,142.21) v1(76.67,16.32) v1(76.67,14.86) v1(76.67,13.59) v1(76.67,12.13) v1(275.93,140.21) v1(277.67,139.83) v1(277.92,141.34) v1(278.26,152.67) v1(278.26,149.59) v1(278.26,146.5) v2(277.19,241.58) v2(278.93,241.2) v2(279.17,242.7) v2(280.14,249.53) v2(280.14,246.45)
UT1_UP5V: length 7.9
  TOP w0.508: UNK2UT1.8 v1(239.13,245.49) ; UT_UP5V.1 v1(19.49,142.21) ; UT1.8 v1(159.13,245.49)
  BOTTOM w0.508: UB1.8 68.92,16.32 v1(68.85,16.25) ; BR902.1 v1(19.38,138.43)
  vias: v1(16.11,291.63) v1(16.57,290.12) v1(19.95,140.7) v1(67.11,13.59) v1(67.11,12.06) v1(81.5,215.14) v1(81.5,199.9) v1(89.23,183.62) v1(89.23,169.4) v1(96.74,199.9) v1(104.47,169.4) v1(108.26,243.18) v1(119.8,289.86) v1(119.8,273.35) v1(135.04,289.86) v1(135.04,273.35) v1(135.04,256.84) v1(147.57,245.49) v1(147.57,244.22) v1(147.57,242.95) v1(150.28,289.86) v1(150.28,273.35) v1(150.28,256.84) v1(160.13,244.22) v1(160.13,242.95) v1(160.13,241.68) v1(161.5,215.14) v1(161.5,199.9) v1(165.52,289.86) v1(165.52,273.35) v1(165.52,256.84) v1(169.23,183.62) v1(169.23,169.4) v1(176.74,199.9) v1(180.76,289.86) v1(180.76,273.35) v1(180.76,256.84) v1(184.47,169.4) v1(188.26,243.18) v1(199.8,289.86) v1(199.8,273.35) v1(199.8,256.84) v1(215.04,289.86) v1(215.04,273.35) v1(215.3,256.84) v1(227.57,245.49) v1(227.57,244.22) v1(227.57,242.95) v1(230.54,256.84) v1(240.13,244.22) v1(240.13,242.95) v1(240.13,241.68) v1(245.78,256.84) v1(261.02,289.86) v1(261.02,273.35) v1(261.02,256.84) v1(276.26,289.86) v1(276.26,273.35) v1(276.26,256.84) v1(278.92,141.34) v1(279.37,139.83) v2(280.17,242.7) v2(280.63,241.2)
UT1_URW00: length 275.1
  L13_CBIT w0.254: K13.8 160.09,183.05 160.09,175.14 158.3,173.35 158.3,162.72 155.72,160.14 155.72,157.74 152.6,154.61 152.6,146.42 130.04,123.87 110.77,123.87 67.58,80.67 67.58,17.33 59.86,9.61 21.14,9.61 UTL1.A01
UT1_URW01: length 204.6
  L13_CBIT w0.254: UTL1.B02 24.45,24.18 54.42,24.18 58.05,27.82 58.05,117.79 46.97,128.87 46.97,162.61 41.43,168.15 41.43,179.59 K28.8
UT1_URW02: length 234.1
  L13_CBIT w0.254: UTL1.A03 25.58,10.25 59.6,10.25 66.94,17.6 66.94,80.94 110.51,124.5 125.42,124.5 137.44,136.52 137.44,159.6 K14.8
UT1_URW03: length 214.8
  L13_CBIT w0.254: K33.8 42.07,190.66 42.07,168.42 47.61,162.88 47.61,129.14 58.69,118.06 58.69,27.55 54.68,23.55 26.36,23.55 UTL1.B03
UT1_URW04: length 217.7
  L13_CBIT w0.254: K20.8 136.8,147.91 136.8,136.78 125.16,125.14 110.25,125.14 66.31,81.2 66.31,17.86 59.33,10.88 27.49,10.88 UTL1.A04
UT1_URW05: length 195.3
  L13_CBIT w0.254: K10.8 65.33,172.22 48.24,155.13 48.24,129.4 59.32,118.32 59.32,27.29 54.95,22.91 30.8,22.91 UTL1.B05
UT1_URW06: length 220.2
  L13_CBIT w0.254: UTL1.A06 31.93,11.52 59.07,11.52 65.67,18.12 65.67,81.46 109.98,125.77 123.36,125.77 129.37,131.79 129.37,159.53 K15.8
UT1_UW07: length 148.2
  L13_CBIT w0.254: SK2.8 59.96,135.98 59.96,27.03 55.21,22.28 32.71,22.28 UTL1.B06
UT1_UW08: length 203.7
  L13_CBIT w0.254: UTL1.A07 33.84,12.15 58.81,12.15 65.04,18.39 65.04,81.73 109.72,126.41 123.1,126.41 128.74,132.05 128.74,147.85 K19.8
UT1_UW09: length 226.5
  L07_SIGNAL w0.254: UTL1.B08 36.33,20.82 56.91,20.82 62.71,26.62 62.71,101.72 69.98,109 69.98,140.01 72.02,142.05 72.02,156.77 74.5,159.25 v1(74.5,199.9) v1(74.5,215.14)
UT1_UW10: length 202.3
  L13_CBIT w0.254: UTL1.A09 38.28,12.79 58.54,12.79 64.4,18.65 64.4,81.99 109.46,127.04 114.99,127.04 121.41,133.46 121.41,160.16 K9.8
UT1_UW11: length 214.9
  L13_CBIT w0.254: v1(89.74,199.9) 85.18,195.33 79.7,195.33 69.43,185.05 69.43,117.01 61.23,108.81 61.23,26.5 55.73,21.01 41.6,21.01 UTL1.B10
UT1_UW12: length 204.1
  L13_CBIT w0.254: K12.8 117.54,171.31 117.54,157.72 114.1,154.27 114.1,138.45 63.77,88.12 63.77,18.91 58.28,13.42 42.73,13.42 UTL1.A11
UT1_UW13: length 141.4
  L13_CBIT w0.254: SK1.8 76.75,136.26 76.75,110.09 61.86,95.2 61.86,26.24 56,20.37 46.04,20.37 UTL1.B12
UT1_UW14: length 180.1
  L13_CBIT w0.254: UTL1.A13 47.17,14.06 58.02,14.06 63.13,19.18 63.13,88.39 104.08,129.33 104.08,162.01 v1(104.47,162.4)
UT1_UW15: length 191.9
  L13_CBIT w0.254: UTL1.B14 50.49,19.74 56.26,19.74 62.5,25.98 62.5,88.65 103.44,129.59 103.44,148.22 103.4,148.22 v1(89.23,162.4) 90.51,163.68 90.51,175.34 v1(89.23,176.62)
UT2_URW00: length 244.1
  L13_CBIT w0.254: UTL2.A01 168.57,9.5 206.27,9.5 214.26,17.49 214.26,70.44 238.02,94.19 238.02,107.15 239.75,108.88 239.75,111.13 244.33,115.71 244.33,132.42 254.88,142.97 254.88,144.82 257.6,147.54 257.6,150.36 260.28,153.04 260.28,165.01 264.99,169.72 264.99,176.46 266.94,178.4 268.38,178.4 UNK2SK2.8
UT2_URW01: length 252.7
  L13_CBIT w0.254: v1(154.5,215.14) v1(154.5,199.9) 165.26,189.14 165.26,161.39 192.9,133.74 192.9,130.75 204.74,118.92 204.74,26 203.25,24.51 172.1,24.51 UTL2.B02
UT2_URW02: length 249
  L13_CBIT w0.254: UTL2.A03 173.01,10.14 206.01,10.14 213.63,17.76 213.63,70.7 236.36,93.43 236.36,111.9 241.18,116.71 241.18,133.8 254.88,147.51 254.88,152.2 257.62,154.94 257.62,165.54 264.36,172.27 264.36,193.71 UNK2K10.8
UT2_URW03: length 232.9
  L13_CBIT w0.254: UTL2.B03 174.01,23.88 203.52,23.88 205.37,25.74 205.37,119.18 193.54,131.01 193.54,134 165.89,161.65 165.89,186.66 168.99,189.76 168.99,199.14 v1(169.74,199.9)
UT2_URW04: length 226.7
  L13_CBIT w0.254: UTL2.A04 174.92,10.77 205.75,10.77 212.99,18.02 212.99,70.96 234.83,92.8 234.83,116.51 239.66,121.33 239.66,134.23 252.18,146.75 252.18,152.37 253.74,153.94 253.74,180.28 UNK2SK1.8
UT2_URW05: length 203.7
  L13_CBIT w0.254: UTL2.B05 178.45,23.24 203.78,23.24 206.01,25.47 206.01,119.44 194.17,131.28 194.17,134.27 169.23,159.22 v1(169.23,162.4) 170.51,163.68 170.51,175.34 v1(169.23,176.62)
UT2_URW06: length 252.6
  L13_CBIT w0.254: UTL2.A06 179.36,11.41 205.49,11.41 212.36,18.28 212.36,71.23 225.83,84.69 225.83,121.11 229.28,124.57 229.28,148.33 239.9,158.95 240.51,158.95 242.65,161.09 242.65,165.81 246.03,169.2 246.03,189.82 243.56,192.28 243.56,212.06 UNK2K33.8
UT2_UW07: length 180.6
  L13_CBIT w0.254: UTL2.B06 180.36,22.61 204.04,22.61 206.64,25.21 206.64,119.71 194.81,131.54 194.81,134.53 184.47,144.87 v1(184.47,162.4)
UT2_UW08: length 234.6
  L13_CBIT w0.254: UNK2K28.8 240.81,200.79 240.81,192.07 240.45,191.71 240.45,175.66 241.68,174.42 241.68,168.99 240.48,167.78 240.48,162.62 226.72,148.87 226.72,128.51 224.98,126.77 224.98,125.02 223.43,123.47 223.43,83.19 211.72,71.49 211.72,18.55 205.22,12.04 181.27,12.04 UTL2.A07
UT2_UW09: length 169.2
  L13_CBIT w0.254: UNK2K9.8 201.16,160.42 201.16,137.16 207.28,131.04 207.28,24.95 204.31,21.97 184.8,21.97 UTL2.B08
UT2_UW10: length 210.8
  L13_CBIT w0.254: UNK2K13.8 239.81,183.32 239.81,175.4 241.05,174.16 241.05,169.25 239.84,168.05 239.84,163.77 225.5,149.43 225.5,132.58 222.7,129.78 222.7,128.3 221.44,127.04 221.44,82.1 211.09,71.75 211.09,18.81 204.96,12.68 185.71,12.68 UTL2.A09
UT2_UW11: length 177.5
  L13_CBIT w0.254: UTL2.B10 189.25,21.34 204.57,21.34 207.91,24.68 207.91,131.3 201.79,137.43 201.79,172.1 UNK2K12.8
UT2_UW12: length 186.5
  L13_CBIT w0.254: UNK2K14.8 223.95,171.95 223.95,151 222.49,149.55 222.49,132.8 218.93,129.23 218.93,80.74 210.45,72.27 210.45,19.07 204.7,13.31 190.16,13.31 UTL2.A11
UT2_UW13: length 161
  L13_CBIT w0.254: UNK2K19.8 215.28,160.18 215.28,137.5 213.85,136.07 213.85,124.96 208.55,119.66 208.55,24.42 204.83,20.7 193.69,20.7 UTL2.B12
UT2_UW14: length 167.6
  L13_CBIT w0.254: UNK2K20.8 223.31,160.27 223.31,151.27 221.86,149.81 221.86,133.06 218.29,129.5 218.29,81 209.82,72.53 209.82,19.34 204.43,13.95 194.6,13.95 UTL2.A13
UT2_UW15: length 169.3
  L13_CBIT w0.254: UNK2K15.8 215.91,171.86 215.91,137.23 214.48,135.81 214.48,124.69 209.18,119.39 209.18,24.16 205.09,20.07 198.14,20.07 UTL2.B14
UT3_URW00: length 248.2
  L13_CBIT w0.254: UTL3.A01 271.41,419.74 233.95,419.74 225.69,411.48 225.69,347.28 183.85,305.44 128.37,305.44 v1(119.8,296.86)
UT3_URW01: length 174.4
  L13_CBIT w0.254: v1(276.26,296.86) v1(261.02,296.86) 235.22,322.67 235.22,402.02 237.7,404.5 267.6,404.5 UTL3.B02
UT3_URW02: length 250.4
  L13_CBIT w0.254: UTL3.A03 266.97,419.1 234.21,419.1 226.33,411.22 226.33,346.71 184.2,304.58 142.76,304.58 v1(135.04,296.86) 119.8,281.62 v1(119.8,280.35)
UT3_URW03: length 199.7
  L13_CBIT w0.254: v1(276.26,263.84) 277.28,264.86 277.28,279.34 v1(276.26,280.35) 272.14,284.48 268.87,284.48 234.58,318.77 234.58,402.28 237.43,405.13 265.7,405.13 UTL3.B03
UT3_URW04: length 251.8
  L13_CBIT w0.254: v1(135.04,263.84) 136.05,264.86 136.05,279.34 v1(135.04,280.35) 135.52,280.84 135.52,285.75 153.46,303.68 184.57,303.68 226.96,346.07 226.96,410.95 234.48,418.47 265.06,418.47 UTL3.A04
UT3_URW05: length 187.5
  L13_CBIT w0.254: v1(261.02,263.84) 262.04,264.86 262.04,279.34 v1(261.02,280.35) 258.71,282.66 258.71,285.75 233.95,310.51 233.95,402.54 237.17,405.76 261.25,405.76 UTL3.B05
UT3_URW06: length 204.1
  L13_CBIT w0.254: v1(150.28,296.86) 156.2,302.79 184.95,302.79 227.6,345.44 227.6,410.69 234.74,417.83 260.62,417.83 UTL3.A06
UT3_UW07: length 178.8
  L13_CBIT w0.254: v1(245.78,263.84) 245.38,264.25 245.38,295.27 233.31,307.34 233.31,402.81 236.91,406.4 259.35,406.4 UTL3.B06
UT3_UW08: length 229
  L13_CBIT w0.254: UTL3.A07 258.71,417.19 235,417.19 228.23,410.43 228.23,344.81 185.32,301.89 165.63,301.89 161.56,297.81 161.56,294 151.4,283.85 151.4,281.47 v1(150.28,280.35) 151.29,279.34 151.29,264.86 v1(150.28,263.84)
UT3_UW09: length 183.1
  L13_CBIT w0.254: v1(230.54,263.84) 230.54,268.09 225.12,273.52 225.12,281.57 215.34,291.35 215.34,296.56 v1(215.04,296.86) 215.04,322.72 232.68,340.36 232.68,403.07 236.64,407.03 254.9,407.03 UTL3.B08
UT3_UW10: length 217.4
  L13_CBIT w0.254: UTL3.A09 254.27,416.56 235.27,416.56 228.87,410.16 228.87,344.17 185.69,300.99 166.64,300.99 164.1,298.45 164.1,281.77 v1(165.52,280.35) 166.53,279.34 166.53,264.86 v1(165.52,263.84)
UT3_UW11: length 174.9
  L13_CBIT w0.254: UTL3.B10 250.46,407.67 236.38,407.67 232.04,403.33 232.04,341 213.63,322.58 213.63,281.76 v1(215.04,280.35) 213.28,278.6 213.28,265.86 v1(215.3,263.84)
UT3_UW12: length 175.2
  L13_CBIT w0.254: UTL3.A11 249.82,415.92 235.53,415.92 229.5,409.9 229.5,343.53 182.83,296.86 v1(180.76,296.86) v1(165.52,296.86)
UT3_UW13: length 173.9
  L13_CBIT w0.254: v1(199.8,263.84) 204.1,268.15 204.1,314.32 231.41,341.63 231.41,403.6 236.12,408.31 246.01,408.31 UTL3.B12
UT3_UW14: length 186.5
  L13_CBIT w0.254: UTL3.A13 245.38,415.29 235.79,415.29 230.14,409.64 230.14,342.9 187.59,300.36 187.59,292.1 180.76,285.26 v1(180.76,280.35) 181.77,279.34 181.77,264.86 v1(180.76,263.84)
UT3_UW15: length 153.7
  L13_CBIT w0.254: UTL3.B14 241.57,408.94 235.85,408.94 230.77,403.86 230.77,342.26 199.8,311.29 v1(199.8,296.86) 200.81,295.85 200.81,281.37 v1(199.8,280.35)
UT4_URW00: length 208
  L13_CBIT w0.254: UTL4.A01 129.17,414.65 129.17,417.83 124.73,422.27 85.27,422.27 77.1,414.11 77.1,346.07 21.56,290.53 UNK2K37.12
UT4_URW01: length 226.9
  L13_CBIT w0.254: UNK2K39.12 21.86,270.5 21.86,276.86 23.76,278.76 23.76,291.84 77.74,345.81 77.74,413.85 85.53,421.64 122.19,421.64 126,417.83 126,412.75 UTL4.B02
UT4_URW02: length 242.9
  L13_CBIT w0.254: UNK2K42.12 23.13,251.45 23.13,276.23 24.4,277.5 24.4,286.38 26.94,288.93 29.48,288.93 31.38,290.83 31.38,298.56 78.37,345.55 78.37,413.59 85.79,421 120.92,421 124.73,417.19 UTL4.A03
UT4_URW03: length 264.3
  L13_CBIT w0.254: UTL4.B03 123.46,412.75 123.46,415.29 118.38,420.37 86.06,420.37 79.01,413.32 79.01,345.29 32.02,298.3 32.02,234.94 28.97,231.9 23.9,231.9 UNK2K36.12
UT4_URW04: length 187.5
  L13_CBIT w0.254: UNK2K34.12 39,291.66 39,303.05 79.64,343.69 79.64,413.06 86.32,419.74 116.47,419.74 UTL4.A04
UT4_URW05: length 206.8
  L13_CBIT w0.254: UTL4.B05 118.38,412.75 118.38,415.29 114.57,419.1 86.58,419.1 80.28,412.8 80.28,343.43 39.64,302.79 39.64,279.4 38.37,278.13 38.37,270.7 UNK2K31.12
UT4_URW06: length 221
  L13_CBIT w0.254: UTL4.A06 112.66,418.47 86.85,418.47 80.91,412.53 80.91,343.16 40.62,302.87 40.62,259.42 38.37,257.18 38.37,250.38 UNK2K40.12
UT4_UW07: length 281.7
  L13_CBIT w0.254: v1(188.26,248.48) 184.65,252.09 107.58,252.09 99.33,260.35 99.33,267.6 81.55,285.38 81.55,308.61 86.63,313.69 86.63,405.98 88.32,407.67 113.3,407.67 UTL4.B06
UT4_UW08: length 170.7
  L13_CBIT w0.254: UTL4.A07 110.76,417.83 87.11,417.83 81.55,412.27 81.55,342.9 53.49,314.84 53.49,291.62 K37.12
UT4_UW09: length 200.7
  L13_CBIT w0.254: v1(108.26,248.48) 107.13,249.61 104.85,249.61 98.69,255.77 98.69,267.33 80.91,285.12 80.91,309.25 85.99,314.32 85.99,406.25 88.05,408.31 108.85,408.31 UTL4.B08
UT4_UW10: length 184.2
  L13_CBIT w0.254: UTL4.A09 106.31,417.19 87.37,417.19 82.18,412.01 82.18,341.63 56.78,316.23 56.78,272.81 K39.12
UT4_UW11: length 164.9
  L13_CBIT w0.254: K34.12 80.28,277.12 80.28,309.88 85.36,314.96 85.36,406.51 87.79,408.94 104.41,408.94 UTL4.B10
UT4_UW12: length 198.4
  L13_CBIT w0.254: K42.12 57.42,253.13 57.42,315.97 82.82,341.37 82.82,411.74 87.64,416.56 101.87,416.56 UTL4.A11
UT4_UW13: length 181.7
  L13_CBIT w0.254: K40.12 73.29,252.29 73.29,304.16 84.72,315.6 84.72,406.77 87.53,409.57 99.96,409.57 UTL4.B12
UT4_UW14: length 212.4
  L13_CBIT w0.254: UTL4.A13 97.42,415.92 87.9,415.92 83.45,411.48 83.45,341.1 58.05,315.7 58.05,233.04 K36.12
UT4_UW15: length 156.8
  L13_CBIT w0.254: K31.12 72.66,271.97 72.66,304.8 84.09,316.23 84.09,407.03 87.26,410.21 95.52,410.21 UTL4.B14
N23628089:
  vias: v1(18.25,138.43)
N24574244: length 2
  BOTTOM w0.231: R89.1 J2.1
N24574268: length 2
  BOTTOM w0.231: R96.1 J3.1
N24574272: length 2
  BOTTOM w0.231: J3.3 R93.1
N24574311: length 2.5
  BOTTOM w0.231: U1.7 R90.1
N24574358: length 16.2
  BOTTOM w0.231: J2.2 70.27,136.45 69.42,137.3 69.42,142.25 U1.3
N24574376: length 2.5
  BOTTOM w0.231: U2.7 R97.1
N24574426: length 13
  BOTTOM w0.231: J3.2 57.96,138.18 57.96,144.49 U2.3
N24574578: length 2
  BOTTOM w0.231: J2.3 R86.1
N24632959: length 62.3
  L22_SIGNAL w0.145: SW1.4 SW1.3 29.5,171.16 53.97,171.16 S1_RST_N.2
  BOTTOM w0.231: R85.2 J1.2 S1_RST_N.2 60.41,177.6 60.41,180.23 61.16,180.98 K10.4
N24632988: length 2
  BOTTOM w0.231: J1.1 C7.1
N24641483: length 2.2
  BOTTOM w0.231: K25.3 82.34,209.74 83.17,210.57 R55.2
N24641485: length 2.2
  BOTTOM w0.231: R56.1 83.22,206.71 82.39,207.54 K25.4
N24641487: length 2.2
  BOTTOM w0.231: R57.2 72.88,210.57 73.71,209.74 K25.6
N24641489: length 2.2
  BOTTOM w0.231: R58.1 72.83,206.71 73.66,207.54 K25.5
N24641552: length 2.2
  BOTTOM w0.231: K26.3 97.58,194.5 98.41,195.33 R59.2
N24641554: length 2.2
  BOTTOM w0.231: K26.4 97.63,192.3 98.46,191.47 R60.1
N24641556: length 2.2
  BOTTOM w0.231: R61.2 88.12,195.33 88.95,194.5 K26.6
N24641558: length 2.2
  BOTTOM w0.231: R62.1 88.07,191.47 88.9,192.3 K26.5
N24641612: length 2.2
  BOTTOM w0.231: K27.5 73.66,192.3 72.83,191.47 R66.1
N24641614: length 2.2
  BOTTOM w0.231: K27.6 73.71,194.5 72.88,195.33 R65.2
N24642432: length 2.2
  BOTTOM w0.231: R45.2 93.8,175 94.63,175.83 K22.6
N24642434: length 2.2
  BOTTOM w0.231: K22.5 96.83,175.78 97.66,174.95 R46.1
N24642442: length 2.2
  BOTTOM w0.231: R47.2 109.04,171.07 109.87,170.24 K23.3
N24642444: length 2.2
  BOTTOM w0.231: R48.1 112.9,171.11 112.07,170.28 K23.4
N24642446: length 2.2
  BOTTOM w0.231: R49.2 109.04,160.77 109.87,161.6 K23.6
N24642448: length 2.2
  BOTTOM w0.231: R50.1 112.9,160.72 112.07,161.55 K23.5
N24642468: length 2.2
  BOTTOM w0.231: R51.2 93.8,171.07 94.63,170.24 K24.3
N24642486: length 2.2
  BOTTOM w0.231: R52.1 97.66,171.11 96.83,170.28 K24.4
